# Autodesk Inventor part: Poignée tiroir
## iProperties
Author: Flavien MARTY
Shininess: 20.0
PropertySet Name: _Private Model Information
Created: 2001-10
Part Number: Poignée tiroir
Material: Par défaut
Document SubType Name: Modélisation
Designer: Flavien MARTY
Control State: 0
Master: False
Checked Out: False
PropertySet Name: Design Tracking Control
Density: 0.0
Volumn: 0.0
Area: 0.0
PropertySet Name: Model Information
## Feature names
1. Base1
